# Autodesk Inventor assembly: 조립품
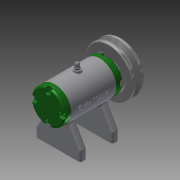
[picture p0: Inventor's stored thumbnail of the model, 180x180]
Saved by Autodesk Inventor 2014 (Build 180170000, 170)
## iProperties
Created: 2018-05
Part Number: 조립품
Document SubType Name: Assembly
Designer: net
Author: net
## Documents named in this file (15)
- C:\Users\net\Desktop\480507V1021\조립품.iam
- C:\Users\net\Desktop\480507V1021\본체.ipt
- C:\Users\net\Desktop\480507V1021\축.ipt
- C:\Users\net\Desktop\480507V1021\베어링 6002.ipt
- C:\Users\net\Desktop\480507V1021\뒤커버.ipt
- C:\Users\net\Desktop\480507V1021\앞커버.ipt
- C:\Users\net\Desktop\480507V1021\오일 실 15 25 7.ipt
- C:\Users\net\Desktop\480507V1021\키 3x3x12.ipt
- C:\Users\net\Desktop\480507V1021\V벨트풀리.ipt
- C:\Users\net\Desktop\480507V1021\와셔 8x17.ipt
- C:\Users\net\Desktop\480507V1021\스프링와셔 8.ipt
- C:\Users\net\Desktop\480507V1021\너트 M8.ipt
- C:\Users\net\Desktop\480507V1021\니플 M6x0.75.ipt
- C:\Users\net\Desktop\480507V1021\와셔 6x11.5.ipt
- C:\Users\net\Desktop\480507V1021\볼트 M6x8.ipt
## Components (1 placed, 1 different names)
1. V벨트풀리:1
